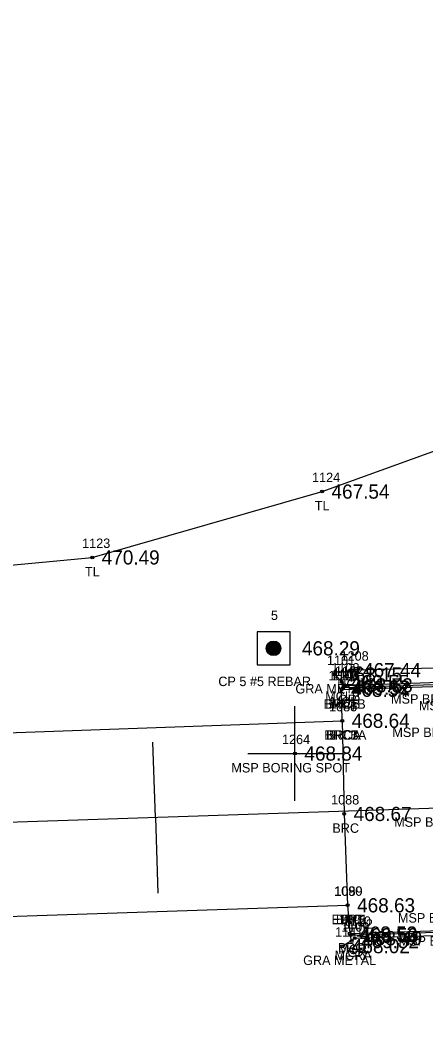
# Model space of a CAD drawing. Extents: x 1784103 to 1787401, y 770251 to 771298.
# Drawn here: x 1785745.6 to 1785788.5, y 770829.9 to 770937.5 of the extents above; entities that cross this region are included whole.
import ezdxf

# ---------------------------------------------------------------- set-up
doc = ezdxf.new("R2010")
doc.units = 0
for name, color, linetype in [('RD_EX_Bridge', 7, 'Continuous'), ('RD_EX_Bridge_txCode', 7, 'Continuous'), ('RD_EX_Conc', 7, 'Continuous'), ('RD_EX_Conc_txCode', 7, 'Continuous'), ('RD_EX_GuardRail', 7, 'Continuous'), ('RD_EX_GuardRail_txCode', 7, 'Continuous'), ('RD_EX_Misc', 7, 'Continuous'), ('RD_EX_Misc_txCode', 7, 'Continuous'), ('RD_EX_Road', 7, 'Continuous'), ('RD_EX_Road_txCode', 7, 'Continuous'), ('RD_EX_TX_Bridge_ELEV', 7, 'Continuous'), ('RD_EX_TX_Conc_ELEV', 7, 'Continuous'), ('RD_EX_TX_GuardRail_ELEV', 7, 'Continuous'), ('RD_EX_TX_Misc_ELEV', 7, 'Continuous'), ('RD_EX_TX_Road_ELEV', 7, 'Continuous'), ('RD_EX_TX_UT_ELEV', 7, 'Continuous'), ('RD_EX_TX_VEG_ELEV', 7, 'Continuous'), ('RD_EX_UT', 7, 'Continuous'), ('RD_EX_UT_txCode', 7, 'Continuous'), ('RD_EX_VEG', 7, 'Continuous'), ('RD_EX_VEG_txCode', 7, 'Continuous'), ('RD_HC_Cl', 7, 'Continuous'), ('RD_HC_Data_Tic', 7, 'Continuous'), ('RD_HC_Survey', 7, 'Continuous'), ('RD_HC_Survey_ELEV', 7, 'Continuous'), ('RD_HC_Survey_txCode', 7, 'Continuous'), ('RD_SMD_Locator', 7, 'Continuous')]:
    doc.layers.add(name, color=color, linetype=linetype)

msp = doc.modelspace()

# ---------------------------------------------------------------- linework, layer by layer
at = {"layer": 'RD_EX_Bridge'}
msp.add_line((1785779.71, 770863.4), (1785779.62, 770866.68), dxfattribs=at)
msp.add_lwpolyline([(1785779.71, 770863.4), (1785779.91, 770853.54), (1785780.28, 770843.87), (1785780.5, 770840.88), (1785825.3, 770842.36), (1785825.31, 770845.6), (1785825, 770854.98), (1785824.57, 770864.86), (1785824.49, 770868.17), (1785779.62, 770866.68)], dxfattribs=at)
at = {"layer": 'RD_EX_Conc'}
for points in [[(1785824.45, 770868.88), (1785824.54, 770868.38), (1785779.78, 770866.9), (1785779.66, 770867.5)], [(1785780.7, 770840.08), (1785780.59, 770840.7), (1785825.26, 770842.31), (1785825.28, 770841.51)]]:
    msp.add_lwpolyline(points, dxfattribs=at)
at = {"layer": 'RD_EX_GuardRail'}
for points in [[(1785778.91, 770868.29), (1785780.03, 770867.15), (1785823.76, 770868.67), (1785825.23, 770869.53)], [(1785779.73, 770839.55), (1785781.04, 770840.39), (1785824.89, 770841.89), (1785826.16, 770841.22)]]:
    msp.add_lwpolyline(points, dxfattribs=at)
at = {"layer": 'RD_EX_Misc'}
for p, q in [((1785774.7, 770854.93), (1785774.7, 770864.93)), ((1785769.7, 770859.93), (1785779.7, 770859.93))]:
    msp.add_line(p, q, dxfattribs=at)
at = {"layer": 'RD_EX_Road'}
for points in [[(1785083.87, 770860.72), (1785132.91, 770853.08), (1785181.89, 770848.53), (1785200.96, 770847.97), (1785215.21, 770848.13), (1785231.38, 770846.18), (1785281.19, 770846.16), (1785330.68, 770847.27), (1785380.41, 770849.82), (1785480.96, 770852.71), (1785580.09, 770856.45), (1785680.2, 770859.84), (1785779.71, 770863.4)], [(1785079.74, 770841.1), (1785077.36, 770829.81), (1785127.59, 770822.23), (1785177.27, 770813.99), (1785180.45, 770828), (1785230.74, 770826.87), (1785281.16, 770827.18), (1785331.14, 770828.42), (1785381.03, 770830.27), (1785481.34, 770833.99), (1785580.1, 770837.94), (1785680.6, 770840.57), (1785780.28, 770843.87)]]:
    msp.add_lwpolyline(points, dxfattribs=at)
at = {"layer": 'RD_EX_UT'}
msp.add_line((1785824.69, 770869.77), (1785780.91, 770868.76), dxfattribs=at)
at = {"layer": 'RD_EX_VEG'}
msp.add_lwpolyline([(1785221.61, 770869.17), (1785226.44, 770862.44), (1785230.83, 770863.64), (1785281.61, 770865.88), (1785330.18, 770866.95), (1785378.64, 770865.28), (1785481.03, 770871.22), (1785579.9, 770882.43), (1785678.49, 770873.66), (1785753.25, 770880.69), (1785777.57, 770887.66), (1785796.72, 770894.6), (1785878.49, 770883.8), (1786077.63, 770894.05), (1786177.75, 770898.7), (1786232.19, 770912.93), (1786276.99, 770915.77), (1786313.89, 770919.94), (1786357.9, 770947.77)], dxfattribs=at)
at = {"layer": 'RD_HC_Cl'}
msp.add_line((1787025.56, 770895.93), (1785279.14, 770836.9), dxfattribs=at)
at = {"layer": 'RD_HC_Data_Tic'}
for q in [(1785759.66, 770861.15), (1785760.2, 770845.16)]:
    msp.add_line((1785759.93, 770853.15), q, dxfattribs=at)
at = {"layer": 'RD_HC_Survey'}
for p, q in [((1785771.81, 770870.63), (1785771.81, 770871.52)), ((1785771.84, 770870.59), (1785771.84, 770871.56)), ((1785771.86, 770870.56), (1785771.86, 770871.59)), ((1785771.89, 770870.54), (1785771.89, 770871.61)), ((1785771.91, 770870.51), (1785771.91, 770871.64)), ((1785771.94, 770870.49), (1785771.94, 770871.66)), ((1785771.96, 770870.47), (1785771.96, 770871.68)), ((1785771.99, 770870.45), (1785771.99, 770871.7)), ((1785772.01, 770870.43), (1785772.01, 770871.71)), ((1785772.04, 770870.42), (1785772.04, 770871.73)), ((1785772.06, 770870.4), (1785772.06, 770871.75)), ((1785772.09, 770870.39), (1785772.09, 770871.76)), ((1785772.11, 770870.38), (1785772.11, 770871.77)), ((1785772.14, 770870.37), (1785772.14, 770871.78)), ((1785772.16, 770870.36), (1785772.16, 770871.79)), ((1785772.19, 770870.35), (1785772.19, 770871.8)), ((1785772.21, 770870.34), (1785772.21, 770871.81)), ((1785772.24, 770870.33), (1785772.24, 770871.82)), ((1785772.26, 770870.33), (1785772.26, 770871.82)), ((1785772.28, 770870.32), (1785772.28, 770871.83)), ((1785772.31, 770870.32), (1785772.31, 770871.83)), ((1785772.33, 770870.31), (1785772.33, 770871.84)), ((1785772.36, 770870.31), (1785772.36, 770871.84)), ((1785772.38, 770870.31), (1785772.38, 770871.84)), ((1785772.41, 770870.31), (1785772.41, 770871.84)), ((1785772.43, 770870.31), (1785772.43, 770871.84)), ((1785772.46, 770870.31), (1785772.46, 770871.84)), ((1785772.48, 770870.31), (1785772.48, 770871.84)), ((1785772.51, 770870.31), (1785772.51, 770871.84)), ((1785772.53, 770870.31), (1785772.53, 770871.84)), ((1785772.56, 770870.31), (1785772.56, 770871.83)), ((1785772.58, 770870.32), (1785772.58, 770871.83)), ((1785772.61, 770870.32), (1785772.61, 770871.83)), ((1785772.63, 770870.33), (1785772.63, 770871.82)), ((1785772.66, 770870.34), (1785772.66, 770871.81)), ((1785772.68, 770870.34), (1785772.68, 770871.81)), ((1785772.71, 770870.35), (1785772.71, 770871.8)), ((1785772.73, 770870.36), (1785772.73, 770871.79)), ((1785772.75, 770870.37), (1785772.75, 770871.78)), ((1785772.78, 770870.38), (1785772.78, 770871.76)), ((1785772.8, 770870.4), (1785772.8, 770871.75)), ((1785772.83, 770870.41), (1785772.83, 770871.74)), ((1785772.85, 770870.43), (1785772.85, 770871.72)), ((1785772.88, 770870.44), (1785772.88, 770871.71)), ((1785772.9, 770870.46), (1785772.9, 770871.69)), ((1785772.93, 770870.48), (1785772.93, 770871.67)), ((1785772.95, 770870.5), (1785772.95, 770871.65)), ((1785772.98, 770870.52), (1785772.98, 770871.62)), ((1785773, 770870.55), (1785773, 770871.6)), ((1785773.03, 770870.58), (1785773.03, 770871.57)), ((1785773.05, 770870.61), (1785773.05, 770871.54)), ((1785773.08, 770870.64), (1785773.08, 770871.51)), ((1785771.69, 770870.9), (1785771.69, 770871.25)), ((1785771.72, 770870.81), (1785771.72, 770871.34)), ((1785771.74, 770870.75), (1785771.74, 770871.4)), ((1785771.76, 770870.7), (1785771.76, 770871.45)), ((1785771.79, 770870.66), (1785771.79, 770871.49)), ((1785773.1, 770870.68), (1785773.1, 770871.47)), ((1785773.13, 770870.73), (1785773.13, 770871.42)), ((1785773.15, 770870.78), (1785773.15, 770871.37)), ((1785773.18, 770870.85), (1785773.18, 770871.3)), ((1785773.2, 770870.96), (1785773.2, 770871.19))]:
    msp.add_line(p, q, dxfattribs=at)
msp.add_lwpolyline([(1785774.19, 770872.82), (1785770.69, 770872.82), (1785770.69, 770869.32), (1785774.19, 770869.32)], close=True, dxfattribs=at)
msp.add_circle((1785772.44, 770871.07), 0.769, dxfattribs=at)
at = {"layer": 'RD_SMD_Locator'}
for centre in [(1785777.57, 770887.66), (1785753.25, 770880.69), (1785772.44, 770871.07), (1785778.91, 770868.29), (1785780.91, 770868.76), (1785779.66, 770867.5), (1785780.03, 770867.15), (1785779.62, 770866.68), (1785779.62, 770866.68), (1785779.78, 770866.9), (1785779.71, 770863.4), (1785779.71, 770863.4), (1785779.71, 770863.4), (1785774.7, 770859.93), (1785779.91, 770853.54), (1785780.28, 770843.87), (1785780.28, 770843.87), (1785780.5, 770840.88), (1785780.59, 770840.7), (1785781.04, 770840.39), (1785779.73, 770839.55), (1785780.7, 770840.08)]:
    msp.add_circle(centre, 0.15, dxfattribs=at)

# ---------------------------------------------------------------- texts
at = {"layer": 'RD_EX_Bridge_txCode'}
for s, p in [('1099', (1785778.24, 770867.68)), ('1100', (1785778.48, 770867.68)), ('BRC1B', (1785777.73, 770864.68)), ('BRCB', (1785777.9, 770864.68)), ('1086', (1785778.3, 770864.4)), ('1087', (1785778.32, 770864.4)), ('BRC1A', (1785777.8, 770861.4)), ('BRCA', (1785777.97, 770861.4)), ('1088', (1785778.53, 770854.54)), ('BRC', (1785778.66, 770851.54)), ('1090', (1785778.85, 770844.87)), ('BRC', (1785779.03, 770841.87)), ('1091', (1785779.39, 770841.88)), ('BRC', (1785779.24, 770838.88))]:
    msp.add_text(s, height=1, dxfattribs=at).set_placement(p)
at = {"layer": 'RD_EX_Conc_txCode'}
for s, p in [('1108', (1785778.56, 770868.5)), ('1107', (1785778.68, 770867.9)), ('MCLB', (1785777.9, 770865.5)), ('MCL', (1785778.49, 770864.9)), ('1110', (1785779.77, 770841.7)), ('1109', (1785779.6, 770841.08)), ('MCR', (1785779.28, 770838.7)), ('MCRA', (1785778.9, 770838.08))]:
    msp.add_text(s, height=1, dxfattribs=at).set_placement(p)
at = {"layer": 'RD_EX_GuardRail_txCode'}
for s, p in [('1101', (1785778.09, 770869.29)), ('1102', (1785778.93, 770868.15)), ('GRA METAL', (1785774.75, 770866.29)), ('GR', (1785779.25, 770865.15)), ('1141', (1785778.95, 770840.55)), ('1142', (1785779.98, 770841.39)), ('GR', (1785780.26, 770838.39)), ('GRA METAL', (1785775.57, 770837.55))]:
    msp.add_text(s, height=1, dxfattribs=at).set_placement(p)
at = {"layer": 'RD_EX_Misc_txCode'}
for s, p in [('MSP BR. DECK OVER BENT', (1785784.87, 770865.21)), ('MSLB WOOD PILES', (1785787.81, 770864.5)), ('1264', (1785773.33, 770860.93)), ('MSP BR. DECK OVER BENT', (1785785.01, 770861.68)), ('MSP BORING SPOT', (1785767.97, 770857.93)), ('MSP BR. DECK OVER BENT', (1785785.2, 770852.18)), ('MSP BR. DECK OVER BENT', (1785785.6, 770842.04)), ('MSP BR. DECK OVER BENT', (1785785.67, 770839.59))]:
    msp.add_text(s, height=1, dxfattribs=at).set_placement(p)
at = {"layer": 'RD_EX_Road_txCode'}
for s, p in [('1085', (1785778.32, 770864.4)), ('EPLB', (1785778.03, 770861.4)), ('1089', (1785778.89, 770844.87)), ('EPRB', (1785778.58, 770841.87))]:
    msp.add_text(s, height=1, dxfattribs=at).set_placement(p)
at = {"layer": 'RD_EX_TX_Bridge_ELEV'}
for s, p in [('468.54', (1785780.62, 770865.93)), ('468.54', (1785780.62, 770865.93)), ('468.64', (1785780.71, 770862.65)), ('468.64', (1785780.71, 770862.65)), ('468.67', (1785780.91, 770852.79)), ('468.63', (1785781.28, 770843.12)), ('468.53', (1785781.5, 770840.13))]:
    msp.add_text(s, height=1.5, dxfattribs=at).set_placement(p)
at = {"layer": 'RD_EX_TX_Conc_ELEV'}
for s, p in [('469.55', (1785780.66, 770866.75)), ('469.52', (1785780.78, 770866.15)), ('469.50', (1785781.59, 770839.95)), ('469.52', (1785781.7, 770839.33))]:
    msp.add_text(s, height=1.5, dxfattribs=at).set_placement(p)
at = {"layer": 'RD_EX_TX_GuardRail_ELEV'}
for s, p in [('468.15', (1785779.91, 770867.54)), ('468.53', (1785781.03, 770866.4)), ('468.02', (1785780.73, 770838.8)), ('468.49', (1785782.04, 770839.64))]:
    msp.add_text(s, height=1.5, dxfattribs=at).set_placement(p)
at = {"layer": 'RD_EX_TX_Misc_ELEV'}
msp.add_text('468.84', height=1.5, dxfattribs=at).set_placement((1785775.7, 770859.18))
at = {"layer": 'RD_EX_TX_Road_ELEV'}
for s, p in [('468.64', (1785780.71, 770862.65)), ('468.63', (1785781.28, 770843.12))]:
    msp.add_text(s, height=1.5, dxfattribs=at).set_placement(p)
at = {"layer": 'RD_EX_TX_UT_ELEV'}
msp.add_text('467.44', height=1.5, dxfattribs=at).set_placement((1785781.91, 770868.01))
at = {"layer": 'RD_EX_TX_VEG_ELEV'}
for s, p in [('467.54', (1785778.57, 770886.91)), ('470.49', (1785754.25, 770879.94))]:
    msp.add_text(s, height=1.5, dxfattribs=at).set_placement(p)
at = {"layer": 'RD_EX_UT_txCode'}
for s, p in [('1208', (1785779.53, 770869.76)), ('UGCB', (1785779.18, 770866.76))]:
    msp.add_text(s, height=1, dxfattribs=at).set_placement(p)
at = {"layer": 'RD_EX_VEG_txCode'}
for s, p in [('1124', (1785776.51, 770888.66)), ('TL', (1785776.8, 770885.66)), ('1123', (1785752.18, 770881.69)), ('TL', (1785752.48, 770878.69))]:
    msp.add_text(s, height=1, dxfattribs=at).set_placement(p)
at = {"layer": 'RD_HC_Survey_ELEV'}
msp.add_text('468.29', height=1.5, dxfattribs=at).set_placement((1785775.44, 770870.32))
at = {"layer": 'RD_HC_Survey_txCode'}
for s, p in [('5', (1785772.16, 770874.07)), ('CP 5 #5 REBAR', (1785766.59, 770867.07))]:
    msp.add_text(s, height=1, dxfattribs=at).set_placement(p)

doc.saveas('drawing.dxf')
